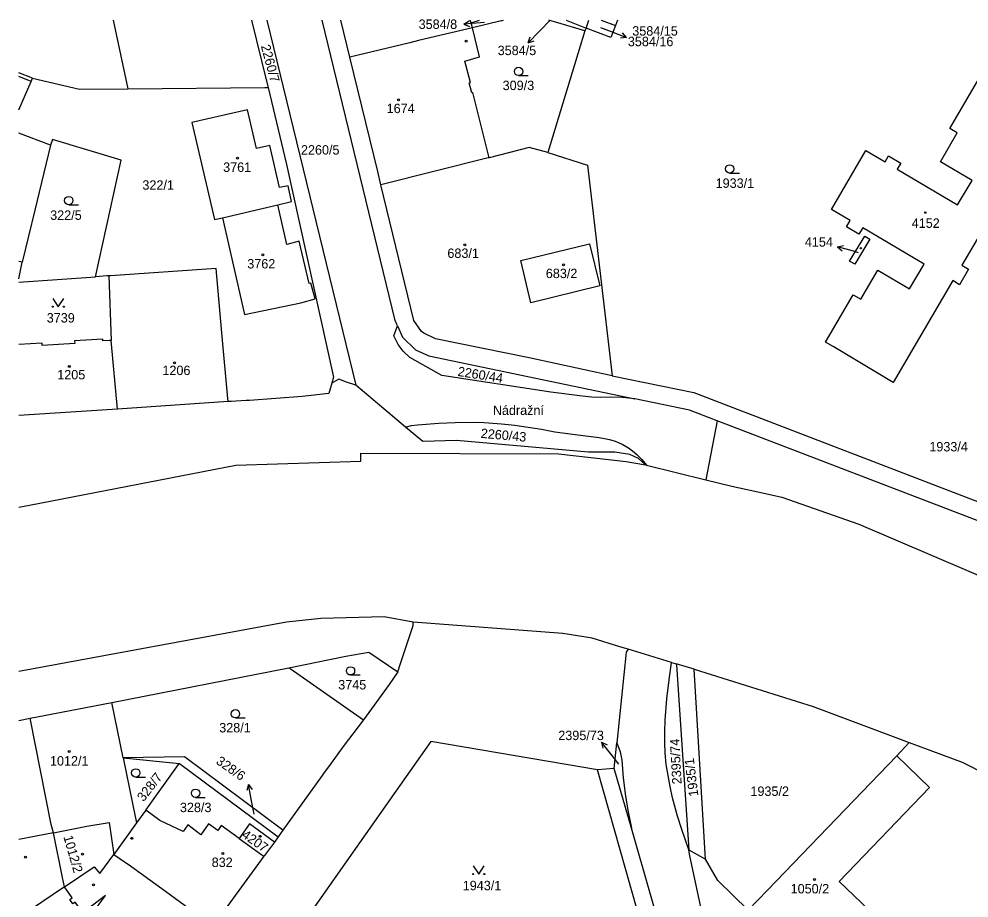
# Model space of a CAD drawing. Extents: x -667048 to -665920, y -1108425 to -1107247.
# Drawn here: x -667043.5 to -666872, y -1107407.4 to -1107248.8 of the extents above; entities that cross this region are included whole.
import ezdxf

# ---------------------------------------------------------------- set-up
doc = ezdxf.new("R2010")
doc.units = 0
for name, color, linetype in [('Default', 7, 'Continuous'), ('Hranice parcel', 7, 'Continuous'), ('Parcelní čísla', 7, 'Continuous'), ('Pop_ PČ_ popisy', 7, 'Continuous'), ('Značky budov', 7, 'Continuous'), ('Značky kultur', 7, 'Continuous')]:
    doc.layers.add(name, color=color, linetype=linetype)

# ---------------------------------------------------------------- blocks, each defined once
blk = doc.blocks.new('3.041')
at = {"layer": 'Default'}
blk.add_line((8, 0), (1758, 0), dxfattribs=at)
blk.add_circle((8, 750), 750, dxfattribs=at)
blk = doc.blocks.new('4.021')
at = {"layer": 'Default'}
blk.add_circle((-7, 1), 175, dxfattribs=at)
blk = doc.blocks.new('3.141')
at = {"layer": 'Default'}
blk.add_lwpolyline([(-1000, 1500), (0, 0), (1000, 1500)], dxfattribs=at)
for centre in [(-1000, 0), (1000, 0)]:
    blk.add_circle(centre, 100, dxfattribs=at)
blk = doc.blocks.new('10291')
at = {"layer": 'Default'}
for p, q in [((0, 3001), (-500, 2001)), ((0, 1), (0, 3001)), ((0, 3001), (500, 2001))]:
    blk.add_line(p, q, dxfattribs=at)

msp = doc.modelspace()

# ---------------------------------------------------------------- linework, layer by layer
at = {"layer": 'Hranice parcel'}
for points in [[(-667026.49, -1107248.98), (-667023.83, -1107261.35)], [(-667001.49, -1107248.98), (-666999.68, -1107256.3), (-666999.01, -1107259.02), (-666998.49, -1107261.14)], [(-666998.76, -1107248.98), (-666982.7, -1107314.88)], [(-666975.18, -1107304.12), (-666975.58, -1107303.2), (-666988.74, -1107248.98)], [(-666983.77, -1107255.67), (-666985.38, -1107248.98)], [(-666961.89, -1107249.46), (-666962.04, -1107248.98)], [(-666961.89, -1107249.46), (-666960.35, -1107248.98)], [(-666961.61, -1107250.34), (-666961.89, -1107249.46)], [(-666956.46, -1107249.08), (-666961.61, -1107250.34)], [(-666956.49, -1107248.98), (-666956.46, -1107249.08)], [(-666956.46, -1107249.08), (-666956.06, -1107248.98)], [(-666941.37, -1107250.9), (-666947.85, -1107248.98)], [(-666944.72, -1107248.98), (-666941.14, -1107250.42)], [(-666941.14, -1107250.42), (-666940.61, -1107248.98)], [(-666935.83, -1107249.96), (-666936.65, -1107252.13), (-666941.14, -1107250.42)], [(-666938.39, -1107248.98), (-666935.83, -1107249.96)], [(-666935.47, -1107248.98), (-666935.83, -1107249.96)], [(-666961.61, -1107250.34), (-666971.35, -1107252.68), (-666972.94, -1107253.07), (-666983.77, -1107255.67)], [(-666958.64, -1107273.8), (-666961.57, -1107262.06), (-666961.76, -1107262.11), (-666962.21, -1107260.31), (-666962.02, -1107260.26), (-666962.99, -1107256.36), (-666960.39, -1107255.62), (-666961.54, -1107250.63), (-666961.61, -1107250.34)], [(-666941.37, -1107250.9), (-666948.03, -1107272.84)], [(-666941.14, -1107250.42), (-666941.37, -1107250.9)], [(-666978.17, -1107278.72), (-666978.73, -1107276.27), (-666983.77, -1107255.67)], [(-667041, -1107259.45), (-667043.46, -1107258.49)], [(-667041.25, -1107260.04), (-667043.46, -1107259.14)], [(-667043.46, -1107265.18), (-667041.25, -1107260.04)], [(-667041.25, -1107260.04), (-667041, -1107259.45)], [(-667041, -1107259.45), (-667032.51, -1107261.42), (-667023.83, -1107261.35)], [(-666870.57, -1107288.53), (-666873.32, -1107293.22), (-666872.12, -1107293.93), (-666873.77, -1107296.75), (-666874.94, -1107295.99), (-666885.72, -1107314.36), (-666896.55, -1107307.89), (-666897.92, -1107307.09), (-666892.93, -1107298.53), (-666891.55, -1107299.33), (-666888.5, -1107294.1), (-666882.77, -1107297.45), (-666880.16, -1107292.99), (-666891.23, -1107286.46), (-666891.9, -1107287.6), (-666894.15, -1107286.27), (-666893.48, -1107285.14), (-666896.87, -1107283.15), (-666890.67, -1107272.51), (-666887.2, -1107274.56), (-666886.56, -1107273.47), (-666884.36, -1107274.77), (-666885.01, -1107275.86), (-666874.09, -1107282.3), (-666871.48, -1107277.89), (-666877.21, -1107274.52), (-666874.16, -1107269.3), (-666875.51, -1107268.51), (-666870.51, -1107259.98)], [(-667023.83, -1107261.35), (-666999.11, -1107261.14)], [(-666999.11, -1107261.14), (-666998.49, -1107261.14)], [(-666998.49, -1107261.14), (-666995.21, -1107275.03)], [(-666996.76, -1107282.31), (-666994.26, -1107281.73), (-666994.9, -1107278.89), (-666996.47, -1107279.18), (-666998.19, -1107271.58), (-667000.59, -1107272.17), (-667002.25, -1107265.15), (-667012.25, -1107267.46), (-667008.18, -1107284.97), (-667006.74, -1107284.64)], [(-667037.76, -1107271.54), (-667043.46, -1107269.37)], [(-667029.65, -1107295.29), (-667025.02, -1107274.24), (-667037.43, -1107270.52), (-667037.76, -1107271.54)], [(-667037.76, -1107271.54), (-667040.62, -1107283.3), (-667042.9, -1107292.64)], [(-666948.03, -1107272.84), (-666951.39, -1107271.97), (-666958.64, -1107273.8)], [(-666958.64, -1107273.8), (-666958.83, -1107273.85), (-666978.17, -1107278.72)], [(-666948.03, -1107272.84), (-666940.86, -1107275.12), (-666936.4, -1107313.14)], [(-666995.21, -1107275.03), (-666986.68, -1107313.43), (-666987, -1107314.51)], [(-666936.4, -1107313.14), (-666951.42, -1107309.95), (-666968.32, -1107306.49), (-666970.42, -1107305.49), (-666970.81, -1107305.19), (-666972.22, -1107303.2), (-666978.17, -1107278.72)], [(-667006.74, -1107284.64), (-666996.76, -1107282.31)], [(-667006.74, -1107284.64), (-667002.74, -1107302.09), (-666992.63, -1107300.01), (-666990.01, -1107299.29), (-666990.78, -1107296.42), (-666991.08, -1107296.5), (-666992.9, -1107288.89), (-666995.13, -1107289.46), (-666996.76, -1107282.31)], [(-666952.88, -1107292.35), (-666940.5, -1107289.32), (-666938.64, -1107296.95), (-666951.08, -1107299.99), (-666952.88, -1107292.35)], [(-666889.93, -1107288.53), (-666892.67, -1107293.03), (-666893.6, -1107292.46), (-666890.86, -1107287.96), (-666889.93, -1107288.53)], [(-667042.9, -1107292.64), (-667043.46, -1107292.51)], [(-667043.46, -1107295.65), (-667042.9, -1107292.64)], [(-667005.74, -1107317.83), (-667005.79, -1107317.23), (-667006.84, -1107305.42), (-667007.88, -1107293.78), (-667026.96, -1107295.11), (-667027.26, -1107295.13)], [(-667043.46, -1107296.25), (-667029.65, -1107295.29)], [(-667027.26, -1107295.13), (-667027.56, -1107295.15), (-667029.65, -1107295.29)], [(-667027.26, -1107295.13), (-667026.8, -1107306.77)], [(-666932.31, -1107317.3), (-666934.63, -1107317.1), (-666936.72, -1107317.03), (-666938.48, -1107317.07), (-666940.13, -1107317.02), (-666941.76, -1107316.84), (-666947.47, -1107316.12), (-666967.17, -1107313.13), (-666972.94, -1107309.84), (-666974.14, -1107308.73), (-666975.05, -1107307.52), (-666975.84, -1107305.96), (-666975.18, -1107304.12)], [(-666975.18, -1107304.12), (-666974.27, -1107306.2), (-666971.94, -1107308.45), (-666969.48, -1107309.54), (-666932.31, -1107317.3)], [(-667026.8, -1107306.77), (-667027.1, -1107306.78), (-667028.33, -1107306.84), (-667028.34, -1107306.54), (-667033.43, -1107306.88), (-667033.4, -1107307.33), (-667039.25, -1107307.71), (-667039.28, -1107307.26), (-667043.46, -1107307.54)], [(-667025.68, -1107319.16), (-667026.8, -1107306.77)], [(-666936.4, -1107313.14), (-666921.72, -1107316.2), (-666866.28, -1107337.45)], [(-666987, -1107314.51), (-666987.55, -1107316.34), (-666992.39, -1107316.89)], [(-666982.7, -1107314.88), (-666984.35, -1107314.3), (-666985.75, -1107313.8), (-666987, -1107314.51)], [(-666973.73, -1107322.43), (-666982.7, -1107314.88)], [(-667005.74, -1107317.83), (-667025.68, -1107319.16)], [(-666992.39, -1107316.89), (-667001.89, -1107317.6), (-667002.46, -1107317.63), (-667005.16, -1107317.8), (-667005.74, -1107317.83)], [(-666922.49, -1107319.35), (-666932.31, -1107317.3)], [(-667025.68, -1107319.16), (-667043.46, -1107320.34)], [(-666917.47, -1107321.28), (-666922.49, -1107319.35)], [(-666972.67, -1107322.15), (-666971.53, -1107321.99), (-666967.72, -1107321.7), (-666964.75, -1107321.58), (-666961.2, -1107321.54), (-666959.52, -1107321.62), (-666956.39, -1107321.85), (-666953.97, -1107322.1), (-666951.59, -1107322.42), (-666949.19, -1107322.81), (-666946.77, -1107323.27), (-666942.65, -1107323.8), (-666938.79, -1107324.3), (-666937.81, -1107324.45), (-666936.9, -1107324.66), (-666935.91, -1107324.98), (-666934.64, -1107325.53), (-666933.5, -1107326.18), (-666932.78, -1107326.68), (-666931.95, -1107327.37), (-666931.08, -1107328.24)], [(-666917.47, -1107321.28), (-666919.51, -1107331.91)], [(-666868.25, -1107340.16), (-666917.47, -1107321.28)], [(-666973.73, -1107322.43), (-666972.67, -1107322.15)], [(-666970.61, -1107325.05), (-666973.73, -1107322.43)], [(-666930.42, -1107329.23), (-666931.67, -1107328.06), (-666933.27, -1107327.34), (-666935.95, -1107326.95), (-666940.7, -1107326.97), (-666964.52, -1107324.83), (-666970.61, -1107325.05)], [(-667043.46, -1107336.88), (-667041.56, -1107336.53), (-667004.35, -1107329.31), (-666981.79, -1107328.54), (-666981.76, -1107327.12), (-666946.09, -1107327.26), (-666933.9, -1107328.62), (-666930.42, -1107329.23)], [(-666931.08, -1107328.24), (-666930.25, -1107329.27)], [(-666930.25, -1107329.27), (-666930.42, -1107329.23)], [(-666930.25, -1107329.27), (-666919.51, -1107331.91)], [(-666919.51, -1107331.91), (-666914.82, -1107333.06)], [(-666914.82, -1107333.06), (-666908.74, -1107334.43), (-666905.84, -1107335.08), (-666891.95, -1107339.94), (-666851.81, -1107357.1), (-666830.89, -1107368.72), (-666808.07, -1107384.76), (-666792.66, -1107397.28), (-666774.87, -1107413.14), (-666760.36, -1107427.5), (-666748.63, -1107440.62), (-666736.58, -1107455.67), (-666731.43, -1107463.41), (-666717.64, -1107484.31), (-666709.65, -1107496.94)], [(-666972.33, -1107357.65), (-666977.54, -1107356.67), (-666988.99, -1107356.96), (-666995.17, -1107357.62), (-667043.46, -1107366.54)], [(-666975.09, -1107366.57), (-666974.6, -1107365.1), (-666972.32, -1107358.25), (-666972.33, -1107357.65)], [(-666933.53, -1107362.52), (-666935.03, -1107362.06), (-666940.03, -1107360.54), (-666945.32, -1107359.7), (-666972.33, -1107357.65)], [(-666984.46, -1107363.79), (-666980.31, -1107363.01), (-666975.09, -1107366.57)], [(-666933.93, -1107363.03), (-666935.57, -1107379.41)], [(-666933.53, -1107362.52), (-666933.93, -1107363.03)], [(-666925.72, -1107364.9), (-666933.53, -1107362.52)], [(-666994.76, -1107365.85), (-666984.46, -1107363.79)], [(-667026.72, -1107372.14), (-666994.76, -1107365.85)], [(-666994.76, -1107365.85), (-666994.55, -1107366), (-666981.32, -1107375.24)], [(-666926.16, -1107368.05), (-666925.72, -1107364.9)], [(-666925.72, -1107364.9), (-666924.86, -1107365.16)], [(-666924.86, -1107365.16), (-666924.85, -1107365.32)], [(-666921.66, -1107366.13), (-666924.86, -1107365.16)], [(-666924.85, -1107365.32), (-666922.6, -1107398.73)], [(-666921.66, -1107366.13), (-666900.19, -1107372.87), (-666882.84, -1107379.32)], [(-666919.6, -1107400.38), (-666921.66, -1107366.13)], [(-666975.09, -1107366.57), (-666976.69, -1107368.86), (-666981.32, -1107375.24)], [(-666922.6, -1107398.73), (-666923.86, -1107395.04), (-666924.63, -1107392.66), (-666925.54, -1107389.3), (-666925.98, -1107387.31), (-666926.66, -1107383.34), (-666926.86, -1107381.2), (-666926.95, -1107379.34), (-666926.95, -1107377.33), (-666926.85, -1107375.34), (-666926.54, -1107371.47), (-666926.16, -1107368.05)], [(-667041.44, -1107374.98), (-667031.42, -1107373.03), (-667026.72, -1107372.14)], [(-667024.66, -1107382.1), (-667026.72, -1107372.14)], [(-667043.46, -1107375.38), (-667041.44, -1107374.98)], [(-667037.23, -1107395.65), (-667037.63, -1107394.13), (-667041.44, -1107374.98)], [(-666981.32, -1107375.24), (-666984.96, -1107380.07)], [(-666939.1, -1107384.26), (-666969.17, -1107379.15), (-666975.49, -1107388.12), (-666997.14, -1107418.9)], [(-666984.96, -1107380.07), (-666987.14, -1107383.08), (-666988.5, -1107384.95), (-666988.74, -1107385.28)], [(-666936.04, -1107384.05), (-666935.57, -1107379.41)], [(-666935.57, -1107379.41), (-666934.96, -1107381.01), (-666934.69, -1107382.56), (-666934.44, -1107385.72), (-666934.03, -1107389.04), (-666933.57, -1107391.85), (-666932.95, -1107394.82)], [(-666885.06, -1107381.72), (-666882.84, -1107379.32)], [(-666882.84, -1107379.32), (-666873.3, -1107382.87), (-666859.63, -1107389.8), (-666844.72, -1107398.67), (-666844.48, -1107399.11), (-666844.08, -1107399.42), (-666833.53, -1107407.7), (-666832.41, -1107408.58), (-666819.89, -1107418.42), (-666818.78, -1107419.28), (-666815.21, -1107422.09), (-666808.14, -1107429.19), (-666803.72, -1107434.01), (-666799.15, -1107440.02), (-666799.37, -1107440.64), (-666800.17, -1107442.88), (-666801.3, -1107445.23), (-666801.72, -1107446.09), (-666802.21, -1107447.25)], [(-666995.85, -1107395.19), (-667013.62, -1107381.91), (-667024.66, -1107382.1)], [(-666911.91, -1107409.62), (-666908.4, -1107406.01), (-666885.06, -1107381.72)], [(-666878.14, -1107421), (-666895.48, -1107404.43), (-666879.17, -1107387.48), (-666885.06, -1107381.72)], [(-667024.66, -1107382.1), (-667022.9, -1107390.66), (-667022.24, -1107393.84)], [(-667024.66, -1107382.1), (-667014.51, -1107383.11)], [(-667020.6, -1107391.58), (-667014.65, -1107383.31), (-667014.51, -1107383.11)], [(-667014.51, -1107383.11), (-666996.71, -1107396.38)], [(-666988.74, -1107385.28), (-666995.85, -1107395.19)], [(-666936.04, -1107384.05), (-666939.1, -1107384.26)], [(-666930.91, -1107413.15), (-666939.1, -1107384.26)], [(-666932.95, -1107394.82), (-666936.04, -1107384.05)], [(-667020.6, -1107391.58), (-667022.24, -1107393.84)], [(-667006.97, -1107394.32), (-667007.61, -1107395.21), (-667009.25, -1107394.03), (-667010.66, -1107395.99), (-667012.97, -1107394.2), (-667013.83, -1107395.38), (-667018.06, -1107393.42), (-667020.6, -1107391.58)], [(-667037.23, -1107395.65), (-667031.19, -1107394.46), (-667027.17, -1107393.78), (-667026.36, -1107399.54)], [(-667022.24, -1107393.84), (-667026.36, -1107399.54)], [(-667037.23, -1107395.65), (-667043.46, -1107396.87)], [(-667035.26, -1107405.41), (-667035.61, -1107403.7), (-667037.23, -1107395.65)], [(-667003.73, -1107396.67), (-667006.97, -1107394.32)], [(-666997.36, -1107397.35), (-667001.88, -1107394), (-667003.73, -1107396.67)], [(-666995.85, -1107395.19), (-666996.71, -1107396.38)], [(-666876.77, -1107557.56), (-666884.34, -1107546.73), (-666886.63, -1107542.65), (-666889.78, -1107536.12), (-666894, -1107526.85), (-666896.26, -1107521.29), (-666898.79, -1107514.08), (-666932.95, -1107394.82)], [(-667003.73, -1107396.67), (-666999.66, -1107399.62)], [(-666997.36, -1107397.35), (-666999.17, -1107399.71)], [(-666996.71, -1107396.38), (-666997.36, -1107397.35)], [(-666913.11, -1107435.5), (-666920.25, -1107409.89), (-666922.49, -1107399.52), (-666922.6, -1107398.73)], [(-666922.6, -1107398.73), (-666919.6, -1107400.38)], [(-667035.26, -1107405.41), (-667029.91, -1107401.81), (-667028.87, -1107403), (-667026.36, -1107399.54)], [(-667026.36, -1107399.54), (-667024.4, -1107400.87), (-667023.75, -1107401.31), (-667017.68, -1107405.72), (-667008.73, -1107412.23), (-667008.37, -1107412.49)], [(-666999.3, -1107399.88), (-667005.88, -1107408.97), (-667008.37, -1107412.49)], [(-666999.66, -1107399.62), (-666999.3, -1107399.88)], [(-666999.17, -1107399.71), (-666999.3, -1107399.88)], [(-666911.91, -1107409.62), (-666917.36, -1107404.22), (-666919.6, -1107400.38)], [(-667035.26, -1107405.41), (-667041.21, -1107409.4)], [(-667030.29, -1107410.32), (-667027.84, -1107406.98), (-667031.91, -1107410.1), (-667033.31, -1107408.14), (-667033.74, -1107408.45), (-667034.31, -1107407.66), (-667033.87, -1107407.35), (-667035.26, -1107405.41)]]:
    msp.add_lwpolyline(points, dxfattribs=at)
at = {"layer": 'Pop_ PČ_ popisy'}
for points in [[(-666959.45, -1107249.43), (-666960.19, -1107249.48)], [(-666947.64, -1107248.98), (-666949.5, -1107250.9)], [(-666938.52, -1107250.33), (-666936.63, -1107251.04)], [(-666891.97, -1107290.96), (-666892.88, -1107290.69)], [(-666935.24, -1107383.27), (-666936.51, -1107381.64)], [(-667001.05, -1107392.25), (-667001.5, -1107389.87)]]:
    msp.add_lwpolyline(points, dxfattribs=at)

# ---------------------------------------------------------------- block references
for p, xscale, yscale, rotation in [((-666960.19, -1107249.48), 0.0010000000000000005, 0.0010000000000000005, 93.99999997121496), ((-666949.5, -1107250.9), 0.001, 0.0010000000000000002, 135.99999999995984), ((-666936.63, -1107251.04), 0.0010000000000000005, 0.0010000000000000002, -110.99999999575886), ((-666892.88, -1107290.69), 0.001, 0.0010000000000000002, 74.00000000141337), ((-666936.51, -1107381.64), 0.0010000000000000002, 0.0010000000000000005, 38.00000002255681), ((-667001.5, -1107389.87), 0.0010000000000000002, 0.0010000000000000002, 10.999999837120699)]:
    msp.add_blockref('10291', p, dxfattribs=dict(at, xscale=xscale, yscale=yscale, rotation=rotation))
at = {"layer": 'Značky budov'}
for p, xscale, yscale in [((-666962.76, -1107252.77), 0.0010000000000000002, 0.0010000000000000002), ((-666974.96, -1107263.35), 0.0010000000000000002, 0.0010000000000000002), ((-667004.04, -1107273.89), 0.0010000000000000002, 0.0010000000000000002), ((-666879.92, -1107283.7), 0.0006700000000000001, 0.0006700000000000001), ((-666963.03, -1107289.55), 0.0010000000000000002, 0.0010000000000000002), ((-666891.55, -1107290.14), 0.0006700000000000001, 0.0006700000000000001), ((-666999.43, -1107291.32), 0.0010000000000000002, 0.0010000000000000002), ((-666945.21, -1107293.12), 0.0010000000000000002, 0.0010000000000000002), ((-667034.37, -1107311.46), 0.0010000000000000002, 0.0010000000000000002), ((-667015.41, -1107310.83), 0.0010000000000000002, 0.0010000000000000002), ((-667034.41, -1107380.96), 0.0010000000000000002, 0.0010000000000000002), ((-667023.07, -1107396.64), 0.0010000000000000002, 0.0010000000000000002), ((-666999.94, -1107396.28), 0.0010000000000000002, 0.0010000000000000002), ((-667042.28, -1107400.02), 0.0010000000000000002, 0.0010000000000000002), ((-667032.01, -1107399.51), 0.0010000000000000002, 0.0010000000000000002), ((-667006.68, -1107399.4), 0.0010000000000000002, 0.0010000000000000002), ((-666899.92, -1107404.07), 0.0010000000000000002, 0.0010000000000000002), ((-667030.02, -1107405.03), 0.0010000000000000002, 0.0010000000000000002)]:
    msp.add_blockref('4.021', p, dxfattribs=dict(at, xscale=xscale, yscale=yscale))
at = {"layer": 'Značky kultur', "xscale": 0.0010000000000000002, "yscale": 0.0010000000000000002}
for name, p in [('3.041', (-666953.32, -1107258.99)), ('3.041', (-666915.24, -1107276.58)), ('3.041', (-667034.48, -1107282.29)), ('3.141', (-667036.37, -1107300.69)), ('3.041', (-666983.65, -1107367.16)), ('3.041', (-667004.41, -1107374.91)), ('3.041', (-667022.39, -1107385.58)), ('3.041', (-667011.6, -1107389.24)), ('3.141', (-666960.5, -1107403.09))]:
    msp.add_blockref(name, p, dxfattribs=at)

# ---------------------------------------------------------------- texts
at = {"layer": 'Parcelní čísla'}
for s, p in [('3584/8', (-666971.35, -1107250.56)), ('3584/15', (-666932.8, -1107251.77)), ('3584/16', (-666933.6, -1107253.68)), ('3584/5', (-666957.09, -1107255.29)), ('309/3', (-666956.19, -1107261.6)), ('1674', (-666977.12, -1107265.76)), ('2260/5', (-666992.58, -1107273.24)), ('3761', (-667006.62, -1107276.36)), ('322/1', (-667021.19, -1107279.58)), ('1933/1', (-666917.76, -1107279.25)), ('322/5', (-667037.83, -1107285.02)), ('4152', (-666882.38, -1107286.46)), ('4154', (-666901.66, -1107289.85)), ('683/1', (-666966.16, -1107291.89)), ('3762', (-667002.27, -1107293.79)), ('683/2', (-666948.4, -1107295.53)), ('3739', (-667038.45, -1107303.55)), ('1206', (-667017.58, -1107313.03)), ('1205', (-667036.56, -1107313.81)), ('1933/4', (-666879.2, -1107326.81)), ('3745', (-666985.86, -1107369.77)), ('328/1', (-667007.33, -1107377.52)), ('2395/73', (-666946.15, -1107378.91)), ('1012/1', (-667037.87, -1107383.5)), ('1935/2', (-666911.48, -1107388.98)), ('328/3', (-667014.42, -1107391.91)), ('832', (-667008.69, -1107401.81)), ('1943/1', (-666963.39, -1107406.01)), ('1050/2', (-666904.23, -1107406.58))]:
    msp.add_text(s, height=1.7, dxfattribs=at).set_placement(p)
for s, rotation, p in [('2260/7', 285, (-666999.83, -1107253.64)), ('2260/44', 351, (-666964.39, -1107313.17)), ('2260/43', 355, (-666960.19, -1107324.35)), ('2395/74', 93, (-666923.89, -1107386.83)), ('328/6', 325, (-667008.04, -1107383.06)), ('1935/1', 97, (-666920.86, -1107388.98)), ('328/7', 52, (-667020.98, -1107390.13)), ('4207', 325, (-667003.42, -1107396.35)), ('1012/2', 286, (-667035.46, -1107396.35))]:
    msp.add_text(s, height=1.7, rotation=rotation, dxfattribs=at).set_placement(p)
at = {"layer": 'Pop_ PČ_ popisy'}
msp.add_text('Nádražní', height=1.7, dxfattribs=at).set_placement((-666957.96, -1107320.23))

doc.saveas('drawing.dxf')
